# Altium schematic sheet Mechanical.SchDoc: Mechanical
size A4; Date: Not used; ApprovedBy: Not used; CheckedBy: Not used; Author: Not used; CompanyName: STMicroelectronics; DrawnBy: Not used; Engineer: Not used; Organization: Not used; Address1: Not used; Address2: Not used; Address3: Not used; Address4: Not used; DocumentNumber: Not used; Revision: Not used; SheetNumber: 11; SheetTotal: 12
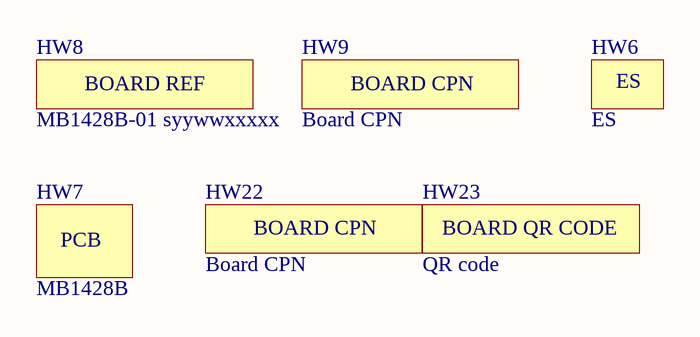
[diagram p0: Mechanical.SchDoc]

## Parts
HW6  value ES  (mechanical)
HW7  value MB1428B  (mechanical)
HW8  value MB1428B-01 syywwxxxxx  [STICKER_25X9]  (mechanical)
HW9  value Board CPN  [STICKER_25X9]  (mechanical)
HW22  value Board CPN  [STICKER_BOARD-CPN_13X3]  (mechanical)
HW23  value QR code  [STICKER_BOARD-QR-CODE_9X9]  (mechanical)

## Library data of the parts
HW6 = MCD-00234: Sticker to mention ES sample; Part_Type: Mechanical; Provided_By: SUBCO
HW7 = MCD-00216: PCB, xxxx for PCB number, Y for PCB revision; Part_Type: Mechanical; Provided_By: SUBCO
HW8 = MCD-00235: Sticker to mention board reference + serial number; Part_Type: Mechanical; Provided_By: SUBCO
HW9 = MCD-00547: Sticker to mention board CPN code; Part_Type: Mechanical; Provided_By: SUBCO
HW22 = MCD-01470: Small sticker to mention board CPN (6 digits CPN + last ones FG); Part_Type: Mechanical; Provided_By: SUBCO
HW23 = MCD-01471: Sticker to mention QR code dor small board size (ie Nucleo-32); Part_Type: Mechanical; Provided_By: SUBCO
